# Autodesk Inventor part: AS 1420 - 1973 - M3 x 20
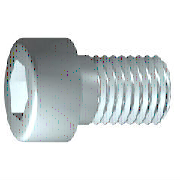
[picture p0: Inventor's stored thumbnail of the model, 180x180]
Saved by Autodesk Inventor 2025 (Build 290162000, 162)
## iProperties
IsCustomPart: 0
Created: 2024-01
Part Number: AS 1420 - 1973 - M3 x 20
Material: Acciaio, Dolce
Description: Viti con esagono incassato metriche ISO
Document SubType Name: Modeling
Standard: AS 1420 - 1973
Designer: R5800u
Standards Organization: AS
Language: it-IT
Size Designation: M3 x 20
Categories: <MemberInstance><Categories><Category DisplayName="Elementi di fissaggio" InternalName="e4da775c-781d-43d5-af7c-5136215cf5a6" Mnemonic="FSTN"><Category DisplayN
Density: 7.85 g/cm^3
Appearance: Semilucidato
Author: R5800u
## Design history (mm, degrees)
body "Solid1"
workplane "Work Plane1"
fillet "Fillet2" dims "d30" = 0.1 (= R)
revolve "Corpo" stored, may be unused: angle "d10" = 90 deg
sketch "Schizzo2"
  geometry: L1 (0, -3.85)-(0, 3.85) reference; L2 (-3.85, 0)-(3.85, 0) reference; L3 (1.443, 0)-(0.722, -1.25); L4 (0.722, -1.25)-(-0.722, -1.25); L5 (-0.722, -1.25)-(-1.443, 0); L6 (-1.443, 0)-(-0.722, 1.25); L7 (-0.722, 1.25)-(0.722, 1.25); L8 (0.722, 1.25)-(1.443, 0); 2 further points
  constraints: 12 end point, 1 coincident, 1 horizontal alignment, 1 point on line, 12 other
extrude "Intaglio" join sketch "Schizzo2" stored distance "d11" = 10; taper "d12" = 0 deg
fillet "Raccordo1" dims "d17" = 0.3 (= RR)
feature "Filettatura" dims "d13" = 12 (= GEL), "d14" = 0
chamfer "Smusso1" distance "d15" = 0.30673 (= -0.5 x SPD + 0.5 x GD); stored, may be unused: second distance "d16" = 0.30673 (= GUL), angle "d27" = 45 deg
sketch "Schizzo1"
  geometry: L1 (-0.867, 0)-(20, 0); L2 (20, 0)-(20, 1.5); L3 (20, 1.5)-(8, 1.5); L4 (8, 1.5)-(7.693, 1.5); L5 (7.693, 1.5)-(0, 1.5); L6 (0, 1.5)-(0, 2.75); L7 (0, 2.75)-(-3, 2.75); L8 (-3, 2.75)-(-3, 1.443); L9 (-3, 1.443)-(-1.7, 1.443); L10 (-1.7, 1.443)-(-0.867, 0); L11 (-7.6, 0)-(24.6, 0) reference; L12 (0, -0.55)-(0, 3.3) reference; L13 (8, 1.5)-(0, 1.5)
  constraints: 22 end point, 6 parallel, 2 collinear, 2 perpendicular, 1 horizontal, 1 point on line
  dimensions: "d1" = 12 distance from line of L3.end L2 (= GEL); "d2" = 0.30683 distance of L4.end L3.end (computed from GAL); "d3" = 3 distance between parallel lines of L8 L6 (= KOH); "d4" = 1.3 distance of L8.end L9.end (= INTI); "d5" = 60 deg angle of L10 L1; "d6" = 3 diameter of L3 L1 (= GD); "d7" = 3 diameter of L5 L1 (= BDM); "d8" = 2.88675 diameter of L9 L1 (= 1.1547 x SW); "d9" = 5.5 diameter of L7 L1 (= KOD); "d26" = 20 distance between parallel lines of L12 L2 (= NLG)
other parameters: "GD" = 3 (= NND) [user parameter; used in 2 equation terms], "NLG" = 20 [user parameter; used in 1 equation term], "GEL" = 12 [user parameter; used in 2 equation terms], "KOD" = 5.5 [user parameter; used in 1 equation term], "KOH" = 3 (= NND) [user parameter; used in 1 equation term], "INTI" = 1.3 [user parameter; used in 1 equation term], "GAL" = 0.30673 (= 0.61345 x PTC) [user parameter; used in 1 equation term], "GUL" = 0.30673 (= 0.61345 x PTC) [user parameter; used in 1 equation term], "BDM" = 3 (= NND) [user parameter; used in 1 equation term], "SW" = 2.5 [user parameter; used in 2 equation terms], "RR" = 0.3 (= 0.1 x NND) [user parameter; used in 1 equation term], "SPD" = 2.38655 (= NND - 1.2269 x PTC) [user parameter; used in 1 equation term], "d19" = 0, "d28" = 0, "d29" = 0, "R" = 0.1 [user parameter; used in 1 equation term], "PHH" = 0.13 [user parameter], "GD1" = 2.38655 (= THREADDIA - 1.2269 x PTC) [user parameter], "THREADDIA" = 3 [user parameter; used in 1 equation term], "FAWI" = 45 deg [user parameter], "PTC" = 0.5 [user parameter; used in 5 equation terms], "KOH1" = 2.7 [user parameter], "NND" = 3 [user parameter; used in 5 equation terms], "TOA" = 30 deg [user parameter], "E0" = 2.8875 (= 1.155 x SW) [user parameter]
